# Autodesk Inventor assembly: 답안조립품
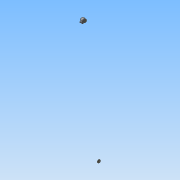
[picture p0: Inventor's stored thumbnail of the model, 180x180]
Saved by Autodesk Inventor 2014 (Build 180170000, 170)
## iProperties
Created: 2016-01
Part Number: 답안조립품
Document SubType Name: Assembly
Designer: Administrator
Author: Administrator
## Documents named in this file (15)
- C:\Users\Administrator\Desktop\460106V1042\답안조립품.iam
- C:\Users\Administrator\Desktop\460106V1042\1-본체.ipt
- C:\Users\Administrator\Desktop\460106V1042\뒤커버.ipt
- C:\Users\Administrator\Desktop\460106V1042\베어링 6203.ipt
- C:\Users\Administrator\Desktop\460106V1042\볼트 M3 x 8.ipt
- C:\Users\Administrator\Desktop\460106V1042\축.ipt
- C:\Users\Administrator\Desktop\460106V1042\부시1.ipt
- C:\Users\Administrator\Desktop\460106V1042\키 - 6 x 6 x 22.ipt
- C:\Users\Administrator\Desktop\460106V1042\키 - 5 x 5 x 18.ipt
- C:\Users\Administrator\Desktop\460106V1042\앞커버.ipt
- C:\Users\Administrator\Desktop\460106V1042\오일씰 28 40 8.ipt
- C:\Users\Administrator\Desktop\460106V1042\부시2.ipt
- C:\Users\Administrator\Desktop\460106V1042\V-벨트풀리.ipt
- C:\Users\Administrator\Desktop\460106V1042\멈춤나사 - M4x10.ipt
- C:\Users\Administrator\Desktop\460106V1042\스퍼기어.ipt
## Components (7 placed, 3 different names)
1. 1-본체:1 — 플러쉬:1
2. V-벨트풀리:1
3. V-벨트풀리:2 — 플러쉬:3
4. ISO 4762 M3 x 8:1
5. ISO 4762 M3 x 8:2
6. ISO 4762 M3 x 8:3
7. ISO 4762 M3 x 8:4
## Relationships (2: Flush 2)
- 플러쉬:1 [Flush]: 1-본체:1
- 플러쉬:3 [Flush]: V-벨트풀리:2
